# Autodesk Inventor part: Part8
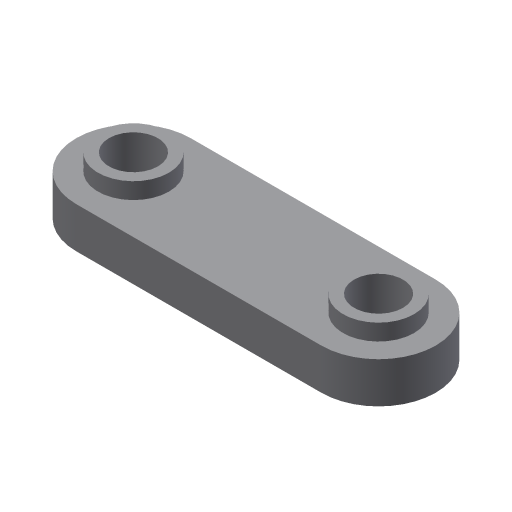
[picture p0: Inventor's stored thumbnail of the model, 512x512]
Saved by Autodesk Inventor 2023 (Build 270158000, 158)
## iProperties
Created: 2002-01
Part Number: Part8
Document SubType Name: Modeling
Designer: ***
Density: 1 g/cm^3
Material: Generic
Appearance: Default
Control State: 0
Master: False
Checked Out: False
Shininess: 77.0
Length Units: 11269
Angle Units: 11279
Time Units: 11290
Mass Units: 11283
Length Display Precision: 3
Angle Display Precision: 2
Density: 0.0
Volumn: 0.0
Area: 0.0
PropertySet Name: Model Information
Author: ***
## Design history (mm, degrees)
sketch "Sketch1"
  geometry: L1 (-33.118, 12.346)-(26.882, 12.361); L2 (-33.111, -15.654)-(26.889, -15.639); C1 r 6 at (-33.114, -1.654); C2 r 6 at (26.886, -1.639); A1 r 14 centre (-33.114, -1.654) between (-33.118, 12.346) and (-33.111, -15.654); A2 r 14 centre (26.886, -1.639) between (26.889, -15.639) and (26.882, 12.361)
  constraints: 4 centre point, 4 end point, 4 point on circle, 4 tangent, 2 coincident, 2 equal radius
  dimensions: "d0" = 60 distance of L1.start L1.end; "d1" = 14 radius of A1; "d2" = 12 diameter of C1
extrude "Extrusion1" new body sketch "Sketch1" distance "d3" = 10; taper "d4" = 0 deg
sketch "Sketch2"
  geometry: C1 r 6 at (26.886, -1.639) reference; C2 r 6 at (-33.114, -1.654) reference; C3 r 8.694 at (-33.114, -1.654); C4 r 8.694 at (26.886, -1.639)
  constraints: 2 centre point, 2 coincident, 1 equal radius
extrude "Extrusion2" join sketch "Sketch2" distance "d5" = 4; taper "d6" = 0 deg
body "Solid1"
